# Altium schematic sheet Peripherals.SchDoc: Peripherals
size A4; Date: Not used; ApprovedBy: Not used; CheckedBy: Not used; Author: Not used; CompanyName: STMicroelectronics; DrawnBy: Not used; Engineer: Not used; Organization: Not used; Address1: Not used; Address2: Not used; Address3: Not used; Address4: Not used; DocumentNumber: Not used; Revision: Not used; SheetNumber: 14; SheetTotal: 23
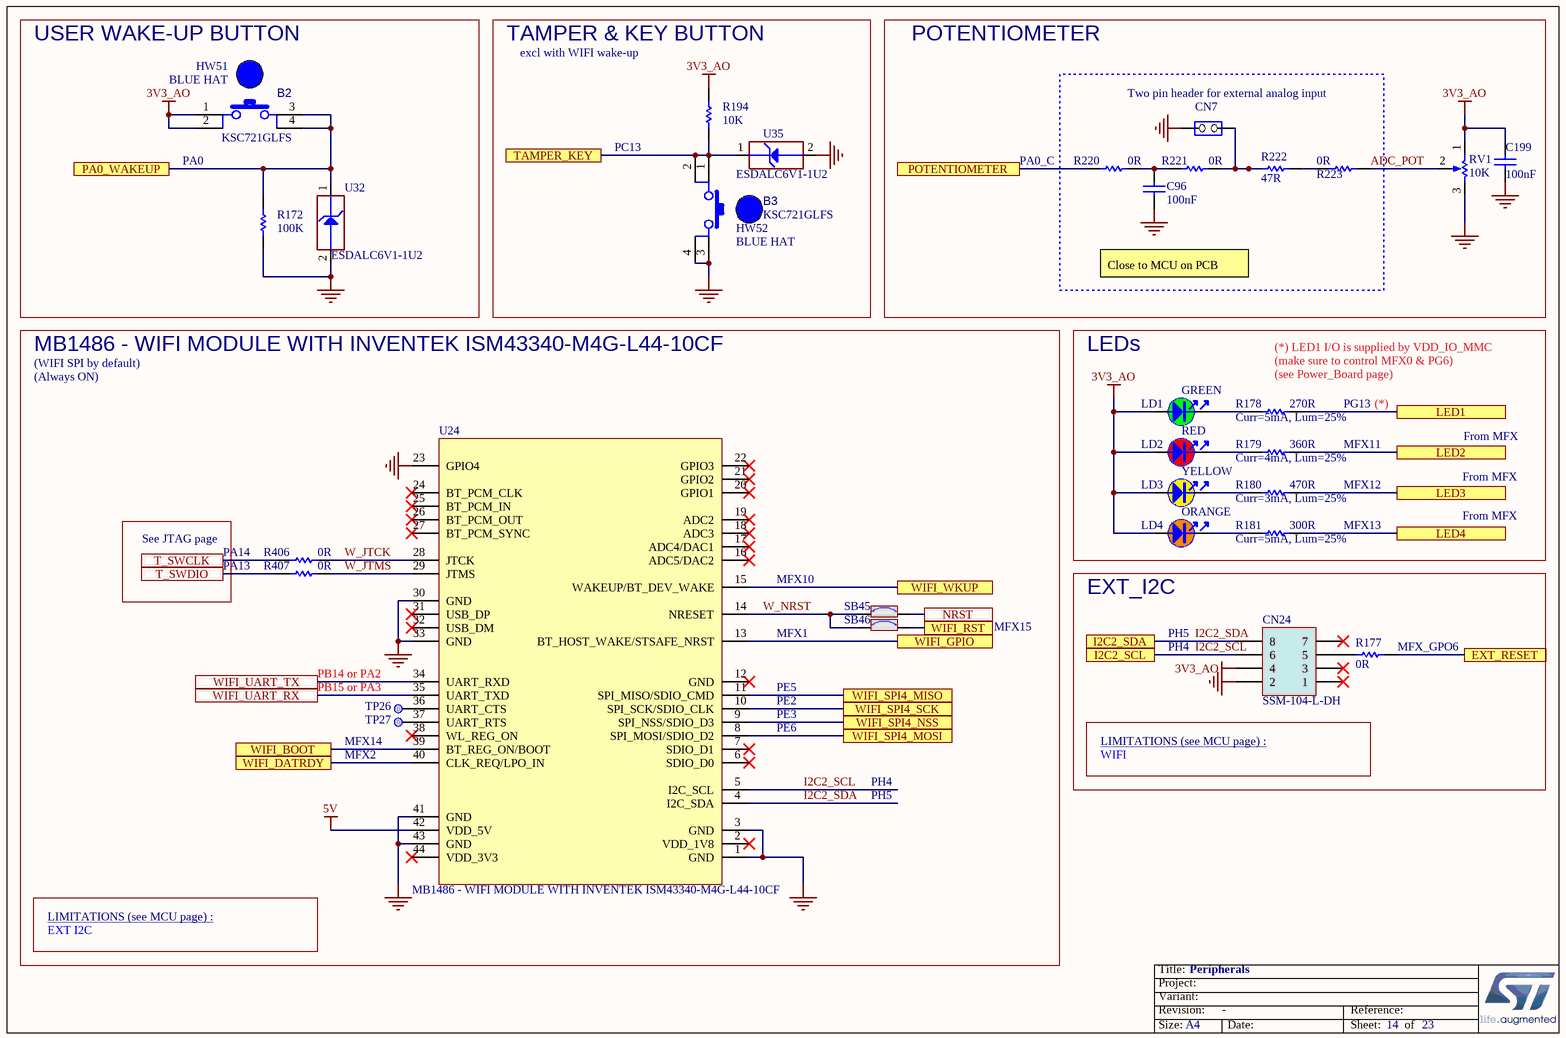
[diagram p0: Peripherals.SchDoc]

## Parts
B2  value KSC721GLFS  [SWI_C&K_KSC721GLFS_BLUE]  (hidden comment: SW_BLUE_KSC721GLFS)
B3  value KSC721GLFS  [SWI_C&K_KSC721GLFS_BLUE]  (hidden comment: SW_BLUE_KSC721GLFS)
C96  value 100nF  [C0603]  (hidden comment: Capacitor)
C199  value 100nF  [C0402]  (hidden comment: Capacitor)
CN7  Jumper_Header 2x1  [CON_SAMTEC_TSW-102-07-G-S]  (value not drawn)
CN24  value SSM-104-L-DH  [CON_SAMTEC_SSM-104-L-DH]  (hidden comment: Socket 4x2)
HW51  value BLUE HAT  (hidden comment: BUTTON_HAT_BLUE)  (mechanical)
HW52  value BLUE HAT  (hidden comment: BUTTON_HAT_BLUE)  (mechanical)
LD1  value GREEN  [LED_0603_OSRAM_LG-Q396-PS-35_GREEN_1A2K_H0P4]  (hidden comment: LED_green)
LD2  value RED  [LED_0603_VISHAY_VLMS1300-GS08_RED_1A2K_H0P8]  (hidden comment: LED_red)
LD3  value YELLOW  [LED_0603_OSRAM_LY-Q396-P1Q2-36_YELLOW_1A2K_H0P4]  (hidden comment: LED_yellow)
LD4  value ORANGE  [LED_0603_OSRAM_LO-Q976-PS-25_ORANGE_1A2K_H0P8]  (hidden comment: LED_orange)
R172  value 100K  [R0402]  (hidden comment: Resistor)
R177  value 0R  [R0402]  (hidden comment: Resistor)
R178  value 270R  [R0402]  (hidden comment: Resistor)
R179  value 360R  [R0402]  (hidden comment: Resistor)
R180  value 470R  [R0402]  (hidden comment: Resistor)
R181  value 300R  [R0402]  (hidden comment: Resistor)
R194  value 10K  [R0402]  (hidden comment: Resistor)
R220  value 0R  [R0603]  (hidden comment: Resistor)
R221  value 0R  [R0603]  (hidden comment: Resistor)
R222  value 47R  [R0603]  (hidden comment: Resistor)
R223  value 0R  [R0603]  (hidden comment: Resistor)
R406  value 0R  [R0402]  (hidden comment: Resistor)
R407  value 0R  [R0402]  (hidden comment: Resistor)
RV1  value 10K  [POT_BOURNS_3386P]  (hidden comment: POTENTIOMETER)
SB45  SB_ON  [SOLDER-BRIDGE_R0603-0R]  (value not drawn)
SB46  SB_ON  [SOLDER-BRIDGE_R0603-0R]  (value not drawn)
TP26  Test Point  [TP_SMD_1MM]  (value not drawn)  (no BOM)
TP27  Test Point  [TP_SMD_1MM]  (value not drawn)  (no BOM)
U24  value MB1486 - WIFI MODULE WITH INVENTEK ISM43340-M4G-L44-10CF  [MOD_WIFI_INVENTEK_ISM43362]  (hidden comment: WIFI MODULE INTERPOSER)
U32  value ESDALC6V1-1U2  [ESD_ST0201]  (hidden comment: ESD-TRANSIL)
U35  value ESDALC6V1-1U2  [ESD_ST0201]  (hidden comment: ESD-TRANSIL)

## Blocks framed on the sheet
USER WAKE-UP BUTTON: B2 HW51 R172 U32
TAMPER & KEY BUTTON: B3 HW52 R194 U35
POTENTIOMETER: C199 RV1
Two pin header for external analog input: C96 CN7 R220-R223
MB1486 - WIFI MODULE WITH INVENTEK ISM43340-M4G-L44-10CF: R406 R407 SB45 SB46 TP26 TP27 U24
LEDs: LD1-LD4 R178-R181
EXT_I2C: CN24 R177

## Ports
EXT_RESET, I2C2_SCL, I2C2_SDA, LED1, LED2, LED3, LED4, NRST, PA0_WAKEUP, POTENTIOMETER, T_SWCLK, T_SWDIO, TAMPER_KEY, WIFI_BOOT, WIFI_DATRDY, WIFI_GPIO, WIFI_RST, WIFI_SPI4_MISO, WIFI_SPI4_MOSI, WIFI_SPI4_NSS, WIFI_SPI4_SCK, WIFI_UART_RX, WIFI_UART_TX, WIFI_WKUP

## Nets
3V3_AO: B2.1 B2.2 C199.1 CN24.4 LD1.1 LD2.1 LD3.1 LD4.1 R194.2 RV1.1(BOT)
5V: U24.42(VDD_5V)
GND: B3.3 B3.4 C96.2 C199.2 CN7.2(NO) CN24.2 R172.1 RV1.3(TOP) U24.1(GND) U24.3(GND) U24.23(GPIO4) U24.30(GND) U24.33(GND) U24.41(GND) U24.43(GND) U32.2(GND) U35.2(GND)
ADC_POT: R223.2 RV1.2(TAP)
EXT_RESET: R177.2 ; port EXT_RESET
I2C2_SCL: CN24.6 U24.5(I2C_SCL) ; port I2C2_SCL
I2C2_SDA: CN24.8 U24.4(I2C_SDA) ; port I2C2_SDA
LED1: R178.2 ; port LED1
LED2: R179.2 ; port LED2
LED3: R180.2 ; port LED3
LED4: R181.2 ; port LED4
NRST: SB45.2 ; port NRST
PA0_WAKEUP: B2.3 B2.4 R172.2 U32.1(IO1) ; port PA0_WAKEUP
POTENTIOMETER: R220.2 ; port POTENTIOMETER
T_SWCLK: R406.1 ; port T_SWCLK
T_SWDIO: R407.1 ; port T_SWDIO
TAMPER_KEY: B3.1 B3.2 R194.1 U35.1(IO1) ; port TAMPER_KEY
W_JTCK: R406.2 U24.28(JTCK)
W_JTMS: R407.2 U24.29(JTMS)
W_NRST: SB45.1 SB46.1 U24.14(NRESET)
WIFI_BOOT: U24.39(BT_REG_ON/BOOT) ; port WIFI_BOOT
WIFI_DATRDY: U24.40(CLK_REQ/LPO_IN) ; port WIFI_DATRDY
WIFI_GPIO: U24.13(BT_HOST_WAKE/STSAFE_NRST) ; port WIFI_GPIO
WIFI_RST: SB46.2 ; port WIFI_RST
WIFI_SPI4_MISO: U24.11(SPI_MISO/SDIO_CMD) ; port WIFI_SPI4_MISO
WIFI_SPI4_MOSI: U24.8(SPI_MOSI/SDIO_D2) ; port WIFI_SPI4_MOSI
WIFI_SPI4_NSS: U24.9(SPI_NSS/SDIO_D3) ; port WIFI_SPI4_NSS
WIFI_SPI4_SCK: U24.10(SPI_SCK/SDIO_CLK) ; port WIFI_SPI4_SCK
WIFI_UART_RX: U24.35(UART_TXD) ; port WIFI_UART_RX
WIFI_UART_TX: U24.34(UART_RXD) ; port WIFI_UART_TX
WIFI_WKUP: U24.15(WAKEUP/BT_DEV_WAKE) ; port WIFI_WKUP
NetC96_1: C96.1 R220.1 R221.1
NetCN7_1: CN7.1(COMMON) R221.2 R222.1
NetCN24_5: CN24.5 R177.1
NetLD1_2: LD1.2 R178.1
NetLD2_2: LD2.2 R179.1
NetLD3_2: LD3.2 R180.1
NetLD4_2: LD4.2 R181.1
NetR222_2: R222.2 R223.1
NetTP26_1: TP26.1 U24.36(UART_CTS)
NetTP27_1: TP27.1 U24.37(UART_RTS)

Not connected (* = marked no-connect by the designer): CN24 1* 3* 7*; U24 2(VDD_1V8)* 6(SDIO_D0)* 7(SDIO_D1)* 12(GND)* 16(ADC5/DAC2)* 17(ADC4/DAC1)* 18(ADC3)* 19(ADC2)* 20(GPIO1)* 21(GPIO2)* 22(GPIO3)* 24(BT_PCM_CLK)* 25(BT_PCM_IN)* 26(BT_PCM_OUT)* 27(BT_PCM_SYNC)* 31(USB_DP)* 32(USB_DM)* 38(WL_REG_ON)* 44(VDD_3V3)*

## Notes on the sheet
- excl with WIFI wake-up
- (near B2) PA0
- PC13
- (near R220) PA0_C
- Close to MCU on PCB
- (WIFI SPI by default)
- (Always ON)
- (near R178) (*) LED1 I/O is supplied by VDD_IO_MMC
  (make sure to control MFX0 & PG6)
  (see Power_Board page)
- (near R178) Curr=5mA, Lum=25%
- PG13
- MFX11
- (*)
- From MFX
- (near R179) Curr=4mA, Lum=25%
- (near R180) Curr=3mA, Lum=25%
- MFX12
- See JTAG page
- PA13
- PA14
- MFX10
- (near R181) Curr=5mA, Lum=25%
- MFX13
- MFX1
- MFX15
- PH5
- PH4
- (near R177) MFX_GPO6
- PB14 or PA2
- PB15 or PA3
- PE5
- PE3
- PE2
- MFX14
- MFX2
- PE6
- LIMITATIONS (see MCU page) :
- WIFI
- EXT I2C

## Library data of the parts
B2 B3 = MCD-00176: Switch HW BLUE High4.3mm 2.25 Newtons; Manufacturer: C&K; Part_Type: Misc; Provided_By: SUBCO
C96 = MCD-00237: Capacitor, MLCC, 100nF, 6V3, X5R, 10%, 0603, T=0,8mm; Manufacturer_Part_Number: CC0603KRX5R5BB104; Manufacturer: YAGEO; Provided_By: SUBCO; ECCN_US: EAR99; ECCN_EU: NEC
C199 = MCD-00006: Capacitor, MLCC, 100nF, 16V, X7R, 10%, 0402, T=0.5mm; Manufacturer_Part_Number: CC0402KRX7R7BB104; Manufacturer: YAGEO; Alternate_Manufacturer_Part_Number: GCM155R71C104KA55D; Alternate_Manufacturer: MURATA; Provided_By: SUBCO; ECCN_US: EAR99; ECCN_EU: NEC
CN7 = MCD-00045: Header, 2x1, 2,54mm, VR, TH, Height 5.84mm/2.54mm; Manufacturer_Part_Number: TSW-102-07-x-S; Manufacturer: SAMTEC; Part_Type: Connector; Alternate_Manufacturer_Part_Number: 313102S111116;313102S111116; Alternate_Manufacturer: JIUBABA; LIANYI; Value: Shunt not fitted; Provided_By: SUBCO
CN24 = MCD-00131: Socket, 4x2, 2.54mm, RA, SMT, Height 5.72mm; Manufacturer: SAMTEC; Part_Type: Connector; Alternate_Manufacturer_Part_Number: F206A-2x04MGF-LA; Alternate_Manufacturer: JIUBABA; Provided_By: SUBCO; ECCN_US: EAR99; ECCN_EU: NEC
HW51 HW52 = MCD-00634: Blue Hat for switch TD0341X-G01-BLU; Part_Type: Mechanical; Manufacturer_Part_Number: 988.16.09.3.00002_SH-517; Manufacturer: JIUBABA; Provided_By: SUBCO
LD1 = MCD-00588: LED Green, 0603 SMD, Forward Voltage Typ=2V, Max=2.5V; Part_Type: Display; Manufacturer_Part_Number: LG Q396-PS-35; Manufacturer: OSRAM OPTO SEMICONDUCTORS; Alternate_Manufacturer_Part_Number: VLMTG1300-GS08; Alternate_Manufacturer: VISHAY SEMICONDUCTOR OPTO DIVISION; Provided_By: SUBCO
LD2 = MCD-00587: LED Red, 0603 SMD, 2V Forward Voltage; Part_Type: Display; Manufacturer_Part_Number: VLMS1300-GS08; Manufacturer: VISHAY; Alternate_Manufacturer_Part_Number: LS Q976-NR-1; Alternate_Manufacturer: OSRAM OPTO SEMICONDUCTORS; Provided_By: SUBCO
LD3 = MCD-01061: LED Yellow, 0603 SMD, Forward Voltage min=1.7V, Typ=2V, Max=2.3V; Part_Type: Display; Manufacturer_Part_Number: LY Q396-P1Q2-36; Manufacturer: OSRAM OPTO SEMICONDUCTORS; Provided_By: SUBCO
LD4 = MCD-00590: LED Orange, 0603 SMD, Forward Voltage Min=1.6V, Max=2.4V; Part_Type: Display; Manufacturer_Part_Number: LO Q976-PS-25; Manufacturer: OSRAM OPTO SEMICONDUCTORS; Alternate_Manufacturer_Part_Number: VLMO1300-GS08; Alternate_Manufacturer: VISHAY SEMICONDUCTOR OPTO DIVISION; Provided_By: SUBCO
R172 = MCD-00059: Resistor,100K,0402,1%,1/16W; Manufacturer_Part_Number: RC0402FR-07100KL; Manufacturer: YAGEO; Alternate_Manufacturer_Part_Number: RT0402FRE07100KL; Provided_By: SUBCO; ECCN_US: EAR99; ECCN_EU: NEC
R177 R406 R407 = MCD-00052: Resistor,0R,0402,5%,1/16W; Manufacturer_Part_Number: RC0402JR-070RL; Manufacturer: YAGEO; Provided_By: SUBCO; ECCN_US: EAR99; ECCN_EU: NEC
R178 = MCD-00441: Resistor,270R,0402,1%,1/16W; Manufacturer_Part_Number: RC0402FR-07270RL; Manufacturer: YAGEO; Provided_By: SUBCO; ECCN_US: EAR99; ECCN_EU: NEC
R179 = MCD-00461: Resistor,360R,0402,1%,1/16W; Manufacturer_Part_Number: RC0402FR-07360RL; Manufacturer: YAGEO; Provided_By: SUBCO; ECCN_US: EAR99; ECCN_EU: NEC
R180 = MCD-00178: Resistor,470R,0402,1%,1/16W; Manufacturer_Part_Number: RC0402FR-07470RL; Manufacturer: YAGEO; Provided_By: SUBCO; ECCN_US: EAR99; ECCN_EU: NEC
R181 = MCD-00449: Resistor,300R,0402,1%,1/16W; Manufacturer_Part_Number: RC0402FR-07300RL; Manufacturer: YAGEO; Provided_By: SUBCO; ECCN_US: EAR99; ECCN_EU: NEC
R194 = MCD-00053: Resistor,10K,0402,1%,1/16W; Manufacturer_Part_Number: RC0402FR-0710KL; Manufacturer: YAGEO; Provided_By: SUBCO; ECCN_US: EAR99; ECCN_EU: NEC
R220 R221 R223 = MCD-00056: Resistor,0R,0603,5%,1/10W; Manufacturer_Part_Number: RC0603JR-070RL; Manufacturer: YAGEO; Provided_By: SUBCO; ECCN_US: EAR99; ECCN_EU: NEC
R222 = MCD-00482: Resistor,47R,0603,1%,1/10W; Manufacturer_Part_Number: RC0603FR-0747RL; Manufacturer: YAGEO; Provided_By: SUBCO; ECCN_US: EAR99; ECCN_EU: NEC
RV1 = MCD-00575: TRIMMER 10K OHM 0.5W PC PIN; Part_Type: Resistor; Manufacturer_Part_Number: 3386P-1-103; Manufacturer: BOURNS; Provided_By: SUBCO; ECCN_US: EAR99; ECCN_EU: NEC
SB45 SB46 = MCD-00071: Solder Bridge ON; Part_Type: Mechanical; Manufacturer_Part_Number: RC0603JR-070RL; Manufacturer: YAGEO; Provided_By: SUBCO
TP26 TP27 = MCD-00074: Test Point 1mm; Part_Type: Mechanical
U24 = MCD-01999: 44 pins Interposer for WIFI module (MB1486 module is with INVENTEK ISM43340-M4G-L44-10CF); Part_Type: Misc; Manufacturer: STMICROELECTRONICS; ECCN_US: 5A002A4; Provided_By: SUBCO with ST control
U32 U35 = MCD-00170: ESD protection 6V1; Part_Type: Diode; Manufacturer: STMICROELECTRONICS; BMS_Part_Number: 9151132; Provided_By: SUBCO with ST control; ECCN_US: EAR99; ECCN_EU: NEC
